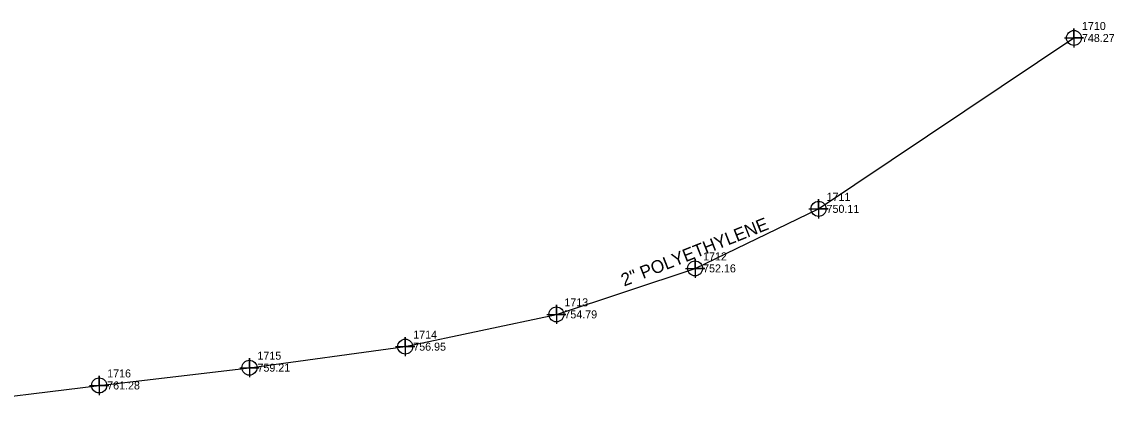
# Model space of a CAD drawing. Extents: x 1622486 to 1624761, y 758733 to 760816.
# Drawn here: x 1623093 to 1623434, y 760139.4 to 760260.3 of the extents above; entities that cross this region are included whole.
import ezdxf

# ---------------------------------------------------------------- set-up
doc = ezdxf.new("R2010")
doc.units = 0
for name, color, linetype in [('Exist Structure Minor Pipes RCP 30 Inch Text', 7, 'Continuous'), ('Exist Utilities Gas UG Line SUE', 7, 'Continuous'), ('Exist Utilities Gas UG Line SUE Cogo Elevation', 7, 'Continuous'), ('Exist Utilities Gas UG Line SUE Cogo Number', 7, 'Continuous'), ('Exist Utilities Gas UG Line SUE Cogo Point CELL', 7, 'Continuous')]:
    doc.layers.add(name, color=color, linetype=linetype)

msp = doc.modelspace()

# ---------------------------------------------------------------- linework, layer by layer
at = {"layer": 'Exist Utilities Gas UG Line SUE'}
msp.add_lwpolyline([(1622547.81, 760209.85), (1622595.31, 760195.24), (1622640.24, 760181.51), (1622683.43, 760171.03), (1622731.01, 760161.58), (1622779.7, 760153.95), (1622829.42, 760147.2), (1622878.02, 760143.06), (1622926.02, 760141.22), (1622974.86, 760139.4), (1623022.29, 760139.76), (1623069.44, 760141), (1623117.1, 760146.8), (1623164.02, 760152.34), (1623212.66, 760158.91), (1623259.85, 760168.99), (1623303.16, 760183.35), (1623341.71, 760201.94), (1623421.45, 760255.29)], dxfattribs=at)
at = {"layer": 'Exist Utilities Gas UG Line SUE Cogo Point CELL'}
for points in [[(1623418.45, 760255.29), (1623424.45, 760255.29), (1623421.45, 760255.29), (1623421.45, 760258.29), (1623421.45, 760252.29)], [(1623338.71, 760201.94), (1623344.71, 760201.94), (1623341.71, 760201.94), (1623341.71, 760204.94), (1623341.71, 760198.94)], [(1623300.16, 760183.35), (1623306.16, 760183.35), (1623303.16, 760183.35), (1623303.16, 760186.35), (1623303.16, 760180.35)], [(1623256.85, 760168.99), (1623262.85, 760168.99), (1623259.85, 760168.99), (1623259.85, 760171.99), (1623259.85, 760165.99)], [(1623209.66, 760158.91), (1623215.66, 760158.91), (1623212.66, 760158.91), (1623212.66, 760161.91), (1623212.66, 760155.91)], [(1623161.02, 760152.34), (1623167.02, 760152.34), (1623164.02, 760152.34), (1623164.02, 760155.34), (1623164.02, 760149.34)], [(1623114.1, 760146.8), (1623120.1, 760146.8), (1623117.1, 760146.8), (1623117.1, 760149.8), (1623117.1, 760143.8)]]:
    msp.add_lwpolyline(points, dxfattribs=at)
for centre in [(1623421.45, 760255.29), (1623341.71, 760201.94), (1623303.16, 760183.35), (1623259.85, 760168.99), (1623212.66, 760158.91), (1623164.02, 760152.34), (1623117.1, 760146.8)]:
    msp.add_circle(centre, 2.34, dxfattribs=at)

# ---------------------------------------------------------------- texts
at = {"layer": 'Exist Structure Minor Pipes RCP 30 Inch Text'}
msp.add_text('2" POLYETHYLENE', height=4, rotation=21.6135, dxfattribs=at).set_placement((1623281, 760177.65))
at = {"layer": 'Exist Utilities Gas UG Line SUE Cogo Elevation'}
for s, p in [('748.27', (1623423.95, 760254.04)), ('750.11', (1623344.21, 760200.69)), ('752.16', (1623305.66, 760182.1)), ('754.79', (1623262.35, 760167.74)), ('756.95', (1623215.16, 760157.66)), ('759.21', (1623166.52, 760151.09)), ('761.28', (1623119.6, 760145.55))]:
    msp.add_text(s, height=2.5, dxfattribs=at).set_placement(p)
at = {"layer": 'Exist Utilities Gas UG Line SUE Cogo Number'}
for s, p in [('1710', (1623423.95, 760257.79)), ('1711', (1623344.21, 760204.44)), ('1712', (1623305.66, 760185.85)), ('1713', (1623262.35, 760171.49)), ('1714', (1623215.16, 760161.41)), ('1715', (1623166.52, 760154.84)), ('1716', (1623119.6, 760149.3))]:
    msp.add_text(s, height=2.5, dxfattribs=at).set_placement(p)

doc.saveas('drawing.dxf')
